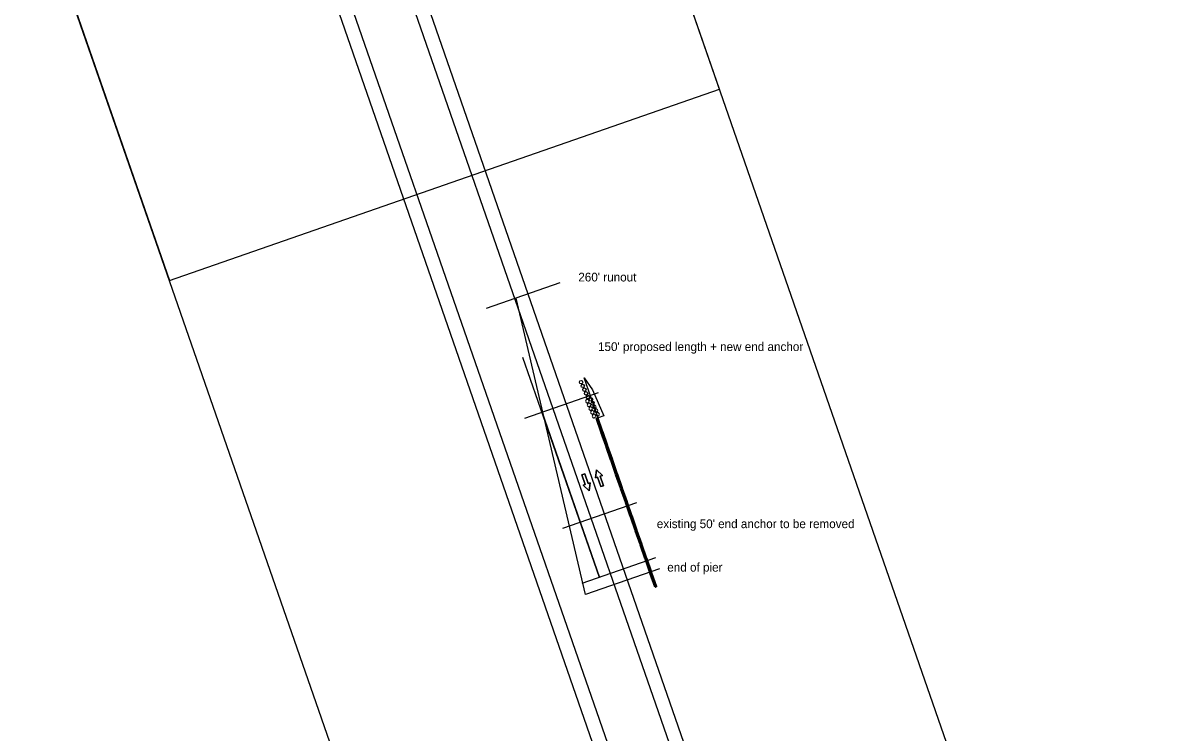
# Model space of a CAD drawing. Extents: x 16415773 to 16419292, y 7112293 to 7123690.
# Drawn here: x 16417123 to 16418117, y 7116913 to 7117522 of the extents above; entities that cross this region are included whole.
import ezdxf

# ---------------------------------------------------------------- set-up
doc = ezdxf.new("R2010")
doc.units = 0
for name, color, linetype in [('Drainage', 7, 'Continuous'), ('NamedBoundary', 7, 'Continuous'), ('PavementMarking', 7, 'Continuous'), ('Stage_3_Pvt_Mk_Removal', 7, 'Continuous'), ('SurNaturalCells', 7, 'Continuous'), ('SurPointsNonDTM', 7, 'Continuous'), ('SurSurveyPoints', 7, 'Continuous'), ('TBR_Path', 7, 'Continuous'), ('Text', 7, 'Continuous')]:
    doc.layers.add(name, color=color, linetype=linetype)

msp = doc.modelspace()

# ---------------------------------------------------------------- linework, layer by layer
at = {"layer": 'Drainage'}
msp.add_line((16417617.9, 7117046.47), (16417552.25, 7117235.39), dxfattribs=at)
at = {"layer": 'NamedBoundary'}
for points in [[(16417248.82, 7117301.47), (16417721.14, 7117465.51), (16417206.86, 7118946.25), (16416734.54, 7118782.2)], [(16417644.63, 7116161.82), (16418116.96, 7116325.86), (16417602.68, 7117806.6), (16417130.35, 7117642.55)]]:
    msp.add_lwpolyline(points, close=True, dxfattribs=at)
at = {"layer": 'PavementMarking'}
for p, q in [((16417969.62, 7116100.87), (16416631.03, 7119955.58)), ((16417958.29, 7116096.93), (16416619.69, 7119951.64)), ((16417958.29, 7116096.93), (16416619.69, 7119951.64))]:
    msp.add_line(p, q, dxfattribs=at)
at = {"layer": 'Stage_3_Pvt_Mk_Removal'}
for p, q in [((16417965.92, 7115922.49), (16416627.37, 7119776.57)), ((16417954.59, 7115918.56), (16416616.03, 7119772.63))]:
    msp.add_line(p, q, dxfattribs=at)
at = {"layer": 'SurNaturalCells'}
for p, q in [((16417616.84, 7117183.6), (16417615.07, 7117182.99)), ((16417619.17, 7117171.18), (16417615.07, 7117182.99)), ((16417619.74, 7117171.37), (16417615.64, 7117183.18)), ((16417620.38, 7117171.6), (16417616.28, 7117183.4)), ((16417620.95, 7117171.79), (16417616.84, 7117183.6)), ((16417620.95, 7117171.79), (16417619.17, 7117171.18)), ((16417621.04, 7117171.51), (16417619.27, 7117170.89)), ((16417623.37, 7117159.08), (16417619.27, 7117170.89)), ((16417623.94, 7117159.28), (16417619.84, 7117171.09)), ((16417624.58, 7117159.5), (16417620.48, 7117171.31)), ((16417625.15, 7117159.7), (16417621.04, 7117171.51)), ((16417625.15, 7117159.7), (16417623.37, 7117159.08)), ((16417625.24, 7117159.41), (16417623.47, 7117158.8)), ((16417627.57, 7117146.99), (16417623.47, 7117158.8)), ((16417628.14, 7117147.19), (16417624.04, 7117159)), ((16417628.78, 7117147.41), (16417624.68, 7117159.22)), ((16417629.35, 7117147.61), (16417625.24, 7117159.41)), ((16417629.35, 7117147.61), (16417627.57, 7117146.99)), ((16417629.44, 7117147.32), (16417627.67, 7117146.7)), ((16417631.77, 7117134.9), (16417627.67, 7117146.7)), ((16417632.34, 7117135.09), (16417628.24, 7117146.9)), ((16417632.98, 7117135.32), (16417628.88, 7117147.12)), ((16417633.55, 7117135.51), (16417629.44, 7117147.32)), ((16417633.55, 7117135.51), (16417631.77, 7117134.9)), ((16417633.64, 7117135.23), (16417631.87, 7117134.61)), ((16417635.97, 7117122.8), (16417631.87, 7117134.61)), ((16417636.54, 7117123), (16417632.44, 7117134.81)), ((16417637.18, 7117123.22), (16417633.08, 7117135.03)), ((16417637.75, 7117123.42), (16417633.64, 7117135.23)), ((16417637.75, 7117123.42), (16417635.97, 7117122.8)), ((16417637.85, 7117123.13), (16417636.07, 7117122.52)), ((16417640.18, 7117110.71), (16417636.07, 7117122.52)), ((16417640.74, 7117110.91), (16417636.64, 7117122.71)), ((16417641.38, 7117111.13), (16417637.28, 7117122.94)), ((16417641.95, 7117111.32), (16417637.85, 7117123.13)), ((16417641.95, 7117111.32), (16417640.18, 7117110.71)), ((16417642.05, 7117111.04), (16417640.27, 7117110.42)), ((16417645.58, 7117099.03), (16417641.48, 7117110.84)), ((16417646.15, 7117099.23), (16417642.05, 7117111.04)), ((16417644.38, 7117098.62), (16417640.27, 7117110.42)), ((16417644.94, 7117098.81), (16417640.84, 7117110.62)), ((16417646.15, 7117099.23), (16417644.38, 7117098.62)), ((16417646.25, 7117098.95), (16417644.47, 7117098.33)), ((16417648.58, 7117086.52), (16417644.47, 7117098.33)), ((16417649.14, 7117086.72), (16417645.04, 7117098.53)), ((16417649.78, 7117086.94), (16417645.68, 7117098.75)), ((16417650.35, 7117087.14), (16417646.25, 7117098.95)), ((16417650.35, 7117087.14), (16417648.58, 7117086.52)), ((16417650.45, 7117086.85), (16417648.67, 7117086.24)), ((16417652.78, 7117074.43), (16417648.67, 7117086.24)), ((16417653.34, 7117074.63), (16417649.24, 7117086.43)), ((16417653.98, 7117074.85), (16417649.88, 7117086.66)), ((16417654.55, 7117075.04), (16417650.45, 7117086.85)), ((16417654.55, 7117075.04), (16417652.78, 7117074.43)), ((16417654.65, 7117074.76), (16417652.87, 7117074.14)), ((16417656.98, 7117062.34), (16417652.87, 7117074.14)), ((16417657.54, 7117062.53), (16417653.44, 7117074.34)), ((16417658.18, 7117062.75), (16417654.08, 7117074.56)), ((16417658.75, 7117062.95), (16417654.65, 7117074.76)), ((16417658.75, 7117062.95), (16417656.98, 7117062.34)), ((16417658.85, 7117062.67), (16417657.07, 7117062.05)), ((16417661.18, 7117050.24), (16417657.07, 7117062.05)), ((16417661.74, 7117050.44), (16417657.64, 7117062.25)), ((16417662.38, 7117050.66), (16417658.28, 7117062.47)), ((16417662.95, 7117050.86), (16417658.85, 7117062.67)), ((16417662.95, 7117050.86), (16417661.18, 7117050.24)), ((16417663.05, 7117050.57), (16417661.28, 7117049.96)), ((16417665.38, 7117038.15), (16417661.28, 7117049.96)), ((16417665.94, 7117038.35), (16417661.84, 7117050.15)), ((16417666.58, 7117038.57), (16417662.48, 7117050.38)), ((16417667.15, 7117038.76), (16417663.05, 7117050.57)), ((16417667.15, 7117038.76), (16417665.38, 7117038.15))]:
    msp.add_line(p, q, dxfattribs=at)
for centre in [(16417615.91, 7117183.44), (16417620.11, 7117171.34), (16417620.11, 7117171.34), (16417624.31, 7117159.25), (16417624.31, 7117159.25), (16417628.51, 7117147.16), (16417628.51, 7117147.16), (16417632.71, 7117135.06), (16417632.71, 7117135.06), (16417636.91, 7117122.97), (16417636.91, 7117122.97), (16417641.11, 7117110.87), (16417641.11, 7117110.87), (16417645.31, 7117098.78), (16417645.31, 7117098.78), (16417649.51, 7117086.69), (16417649.51, 7117086.69), (16417653.71, 7117074.59), (16417653.71, 7117074.59), (16417657.91, 7117062.5), (16417657.91, 7117062.5), (16417662.11, 7117050.41), (16417662.11, 7117050.41), (16417666.31, 7117038.31)]:
    msp.add_circle(centre, 0.0521, dxfattribs=at)
for centre, start, end in [((16417615.96, 7117183.29), 19.15262, 199.15262), ((16417620.06, 7117171.48), 199.15262, 19.15262), ((16417620.16, 7117171.2), 19.15262, 199.15262), ((16417624.26, 7117159.39), 199.15262, 19.15262), ((16417624.36, 7117159.11), 19.15262, 199.15262), ((16417628.46, 7117147.3), 199.15262, 19.15262), ((16417628.56, 7117147.01), 19.15262, 199.15262), ((16417632.66, 7117135.2), 199.15262, 19.15262), ((16417632.76, 7117134.92), 19.15262, 199.15262), ((16417636.86, 7117123.11), 199.15262, 19.15262), ((16417636.96, 7117122.83), 19.15262, 199.15262), ((16417641.06, 7117111.02), 199.15262, 19.15262), ((16417641.16, 7117110.73), 19.15262, 199.15262), ((16417645.26, 7117098.92), 199.15262, 19.15262), ((16417645.36, 7117098.64), 19.15262, 199.15262), ((16417649.46, 7117086.83), 199.15262, 19.15262), ((16417649.56, 7117086.54), 19.15262, 199.15262), ((16417653.66, 7117074.74), 199.15262, 19.15262), ((16417653.76, 7117074.45), 19.15262, 199.15262), ((16417657.86, 7117062.64), 199.15262, 19.15262), ((16417657.96, 7117062.36), 19.15262, 199.15262), ((16417662.06, 7117050.55), 199.15262, 19.15262), ((16417662.16, 7117050.26), 19.15262, 199.15262), ((16417666.26, 7117038.46), 199.15262, 19.15262)]:
    msp.add_arc(centre, 0.281, start, end, dxfattribs=at)
at = {"layer": 'SurPointsNonDTM'}
for p, q in [((16417616.84, 7117183.6), (16417604.95, 7117217.84)), ((16417604.95, 7117217.84), (16417611.96, 7117207.57)), ((16417611.96, 7117207.57), (16417621.8, 7117185.32)), ((16417621.8, 7117185.32), (16417616.84, 7117183.6))]:
    msp.add_line(p, q, dxfattribs=at)
at = {"layer": 'SurSurveyPoints'}
for centre in [(16417602.21, 7117214.07), (16417603.64, 7117210.88), (16417605.07, 7117207.68), (16417606.5, 7117204.49), (16417607.94, 7117201.3), (16417610.77, 7117199.25), (16417610.77, 7117199.25)]:
    msp.add_circle(centre, 1.5, dxfattribs=at)
for centre, start, end in [((16417607.58, 7117197.82), 119.15281, 299.15281), ((16417607.58, 7117197.82), 299.15281, 119.15281), ((16417609.01, 7117194.62), 119.15281, 299.15281), ((16417609.01, 7117194.62), 299.15281, 119.15281), ((16417610.44, 7117191.43), 119.15281, 299.15281), ((16417610.44, 7117191.43), 299.15281, 119.15281), ((16417612.2, 7117196.05), 119.15281, 299.15281), ((16417612.2, 7117196.05), 299.15281, 119.15281), ((16417613.64, 7117192.86), 119.15281, 299.15281), ((16417613.64, 7117192.86), 299.15281, 119.15281), ((16417615.07, 7117189.67), 119.15281, 299.15281), ((16417615.07, 7117189.67), 299.15281, 119.15281), ((16417611.87, 7117188.23), 119.15281, 299.15281), ((16417611.87, 7117188.23), 299.15281, 119.15281), ((16417613.31, 7117185.04), 119.15281, 299.15281), ((16417613.31, 7117185.04), 299.15281, 119.15281), ((16417616.5, 7117186.47), 119.15281, 299.15281), ((16417616.5, 7117186.47), 299.15281, 119.15281)]:
    msp.add_arc(centre, 1.5, start, end, dxfattribs=at)
at = {"layer": 'TBR_Path'}
for p, q in [((16417584.05, 7117299.37), (16417520.77, 7117277.39)), ((16417606.08, 7117031.78), (16417546.36, 7117286.27)), ((16417616.86, 7117204.9), (16417553.58, 7117182.92)), ((16417568.67, 7117188.16), (16417617.9, 7117046.47)), ((16417649.67, 7117110.44), (16417586.39, 7117088.46)), ((16417666.08, 7117063.2), (16417602.79, 7117041.23)), ((16417669.36, 7117053.76), (16417606.08, 7117031.78))]:
    msp.add_line(p, q, dxfattribs=at)
at = {"layer": 'Text'}
for points in [[(16417602.96, 7117134.61), (16417605.32, 7117135.43), (16417608.2, 7117127.17), (16417609.97, 7117127.78), (16417609.06, 7117120.85), (16417604.06, 7117125.73), (16417605.83, 7117126.35)], [(16417621.57, 7117125.2), (16417619.21, 7117124.38), (16417616.34, 7117132.64), (16417614.56, 7117132.03), (16417615.47, 7117138.96), (16417620.47, 7117134.08), (16417618.7, 7117133.46)]]:
    msp.add_lwpolyline(points, close=True, dxfattribs=at)
for points in [[(16417605.83, 7117126.35), (16417604.06, 7117125.73), (16417609.06, 7117120.85), (16417609.97, 7117127.78), (16417608.2, 7117127.17), (16417605.32, 7117135.43), (16417602.96, 7117134.61), (16417605.83, 7117126.35)], [(16417618.7, 7117133.46), (16417620.47, 7117134.08), (16417615.47, 7117138.96), (16417614.56, 7117132.03), (16417616.34, 7117132.64), (16417619.21, 7117124.38), (16417621.57, 7117125.2), (16417618.7, 7117133.46)]]:
    msp.add_lwpolyline(points, dxfattribs=at)

# ---------------------------------------------------------------- texts
at = {"layer": 'TBR_Path'}
for s, p in [("260' runout", (16417599.82, 7117300.55)), ("150' proposed length + new end anchor", (16417616.71, 7117240.82)), ("existing 50' end anchor to be removed", (16417667.19, 7117088.76)), ('end of pier', (16417676.16, 7117051.46))]:
    msp.add_text(s, height=7.5, dxfattribs=at).set_placement(p)

doc.saveas('drawing.dxf')
